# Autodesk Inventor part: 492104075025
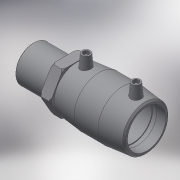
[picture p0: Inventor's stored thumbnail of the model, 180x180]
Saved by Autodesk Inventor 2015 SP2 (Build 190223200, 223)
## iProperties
Created: 2017-06
Part Number: 492104075025
Material: Generic
Description: PLASSON Male Transition Coupler 75 x 2.1/2"
Document SubType Name: Modeling
Designer: KIM
Mass: 535.447 g
Surface Area: 1010.96 cm^2
Volume: 535.447 cm^3
Density: 1 g/cm^3
Appearance: Default
Author: KIM
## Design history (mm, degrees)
derived "492104.ipt"
feature "Solid1::492104.ipt"
tag "TaggingFeature1"
body "Solid1"
other parameters: "d0" = 126, "d1" = 75, "d2" = 98, "d3" = 61, "d4" = 42, "d5" = 88.2, "d6" = 71.25, "d7" = 75, "d8" = 168 deg, "d10" = 24.4, "d11" = 8.13333, "d29" = 64, "d30" = 14, "d31" = 44.1, "d34" = 5 deg, "d41" = 4, "d42" = 14, "d43" = 0, "d48" = 3, "d49" = 0, "d57" = 59, "d58" = 75.184, "d59" = 60.1472, "d60" = 41.4, "d61" = 98, "d62" = 1.50368, "d65" = 2.94, "d70" = 0.1, "d71" = 46, "d72" = 11.5, "d73" = 24.4, "d75" = 0, "d_" = 75, "L_" = 172, "L_1" = 61, "D_1" = 98, "A_" = 64, "d_2" = 12, "L_2" = 46, "D_" = 59, "R_" = 75.184
